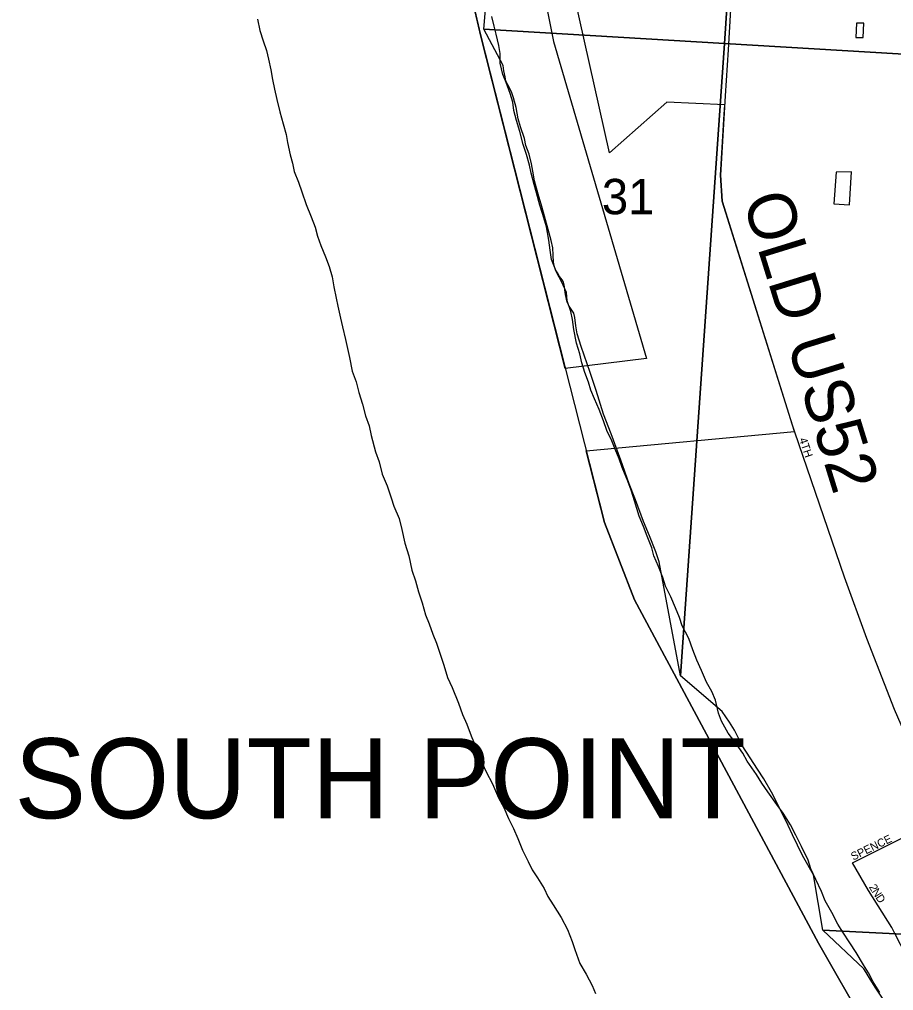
# Model space of a CAD drawing. Extents: x 1949938.81 to 1949945.61, y 152207.65 to 152214.09.
# Drawn here: x 1949939.393 to 1949940.427, y 152209.158 to 152210.308 of the extents above; entities that cross this region are included whole.
import ezdxf

# ---------------------------------------------------------------- set-up
doc = ezdxf.new("R2010")
doc.units = 0
for name, color, linetype in [('GM_X_City_Street', 7, 'Continuous'), ('GM_X_City_Street_Text', 7, 'Continuous'), ('GM_X_Corporation', 7, 'Continuous'), ('GM_X_Corporation_Text', 7, 'Continuous'), ('GM_X_County', 7, 'Continuous'), ('GM_X_County_Road', 7, 'Continuous'), ('GM_X_County_Road_Text', 7, 'Continuous'), ('GM_X_Major_River', 7, 'Continuous'), ('GM_X_Section', 7, 'Continuous'), ('GM_X_Section_Text', 7, 'Continuous'), ('GM_X_Township', 7, 'Continuous')]:
    doc.layers.add(name, color=color, linetype=linetype)

msp = doc.modelspace()

# ---------------------------------------------------------------- linework, layer by layer
at = {"layer": 'GM_X_City_Street'}
for points in [[(1949940.2381, 152210.3883), (1949940.2314, 152210.2719), (1949940.2281, 152210.2175)], [(1949940.3073, 152209.828), (1949940.3099, 152209.8198), (1949940.3687, 152209.6481), (1949940.3953, 152209.5754), (1949940.428, 152209.4915), (1949940.4841, 152209.3624), (1949940.5115, 152209.3013), (1949940.5424, 152209.2289)], [(1949940.3786, 152209.3094), (1949940.4345, 152209.3375), (1949940.4841, 152209.3624)], [(1949940.4828, 152209.1185), (1949940.4627, 152209.1592), (1949940.4558, 152209.1732), (1949940.4287, 152209.2261), (1949940.4251, 152209.2332), (1949940.3975, 152209.2768), (1949940.3786, 152209.3094)]]:
    msp.add_lwpolyline(points, dxfattribs=at)
at = {"layer": 'GM_X_Corporation'}
for points in [[(1949939.8861, 152210.5185), (1949939.9781, 152210.5158), (1949940.0249, 152210.2816), (1949940.1348, 152209.9064), (1949940.0387, 152209.8948), (1949939.9388, 152210.288), (1949939.9215, 152210.363), (1949939.8931, 152210.4482)], [(1949940.3825, 152210.2866), (1949940.3911, 152210.2866), (1949940.3919, 152210.3034), (1949940.3833, 152210.3034)], [(1949940.375, 152210.0885), (1949940.3773, 152210.1274), (1949940.3594, 152210.127), (1949940.3564, 152210.0896)]]:
    msp.add_lwpolyline(points, close=True, dxfattribs=at)
msp.add_lwpolyline([(1949940.3947, 152209.1158), (1949940.3383, 152209.2145), (1949940.1207, 152209.6209), (1949940.0851, 152209.7125), (1949940.0635, 152209.7974), (1949940.3098, 152209.8201), (1949940.2242, 152210.0926), (1949940.2224, 152210.1234), (1949940.2269, 152210.1955), (1949940.2275, 152210.2069), (1949940.1588, 152210.2098), (1949940.0909, 152210.1498), (1949940.0091, 152210.5167)], dxfattribs=at)
at = {"layer": 'GM_X_County'}
msp.add_lwpolyline([(1949939.7311, 152211.8376), (1949939.7258, 152211.7457), (1949939.7413, 152211.6273), (1949939.7962, 152211.2639), (1949939.7977, 152211.2171), (1949939.8117, 152211.0959), (1949939.8776, 152210.6025), (1949939.8931, 152210.4482), (1949939.9215, 152210.363), (1949939.9378, 152210.2911), (1949940.0851, 152209.7125), (1949940.1207, 152209.6209), (1949940.3383, 152209.2145), (1949940.3947, 152209.1158)], dxfattribs=at)
at = {"layer": 'GM_X_County_Road'}
msp.add_lwpolyline([(1949940.2281, 152210.2175), (1949940.2224, 152210.1234), (1949940.2242, 152210.0926), (1949940.3073, 152209.828)], dxfattribs=at)
at = {"layer": 'GM_X_Major_River'}
for points in [[(1949939.6744, 152210.308), (1949939.6774, 152210.2947), (1949939.6812, 152210.2825), (1949939.685, 152210.2711), (1949939.6876, 152210.2608), (1949939.6903, 152210.2483), (1949939.6921, 152210.2365), (1949939.6944, 152210.2251), (1949939.6974, 152210.2129), (1949939.7008, 152210.1985), (1949939.705, 152210.1841), (1949939.7084, 152210.1715), (1949939.7099, 152210.162), (1949939.7133, 152210.1476), (1949939.716, 152210.1377), (1949939.7178, 152210.1278), (1949939.7228, 152210.1153), (1949939.7269, 152210.1038), (1949939.7322, 152210.0886), (1949939.7379, 152210.0742), (1949939.7428, 152210.062), (1949939.7454, 152210.0514), (1949939.7496, 152210.0404), (1949939.7549, 152210.0267), (1949939.7594, 152210.0153), (1949939.7628, 152210.0031), (1949939.7647, 152209.9913), (1949939.7674, 152209.978), (1949939.7696, 152209.9685), (1949939.7726, 152209.9541), (1949939.7749, 152209.9438), (1949939.7787, 152209.929), (1949939.781, 152209.9184), (1949939.7832, 152209.9077), (1949939.7866, 152209.8914), (1949939.7912, 152209.8789), (1949939.7942, 152209.8663), (1949939.7987, 152209.8526), (1949939.8021, 152209.8386), (1949939.8067, 152209.8268), (1949939.8089, 152209.8154), (1949939.8142, 152209.796), (1949939.8184, 152209.7843), (1949939.8222, 152209.7694), (1949939.8278, 152209.7558), (1949939.8327, 152209.7417), (1949939.8358, 152209.7318), (1949939.8422, 152209.717), (1949939.8452, 152209.7041), (1949939.849, 152209.6881), (1949939.8535, 152209.6729), (1949939.8573, 152209.6559), (1949939.8615, 152209.6433), (1949939.8649, 152209.6304), (1949939.8694, 152209.6175), (1949939.8732, 152209.6031), (1949939.8777, 152209.5924), (1949939.8819, 152209.5803), (1949939.8864, 152209.5696), (1949939.8909, 152209.5552), (1949939.8951, 152209.5434), (1949939.8992, 152209.529), (1949939.9049, 152209.5172), (1949939.9125, 152209.4986), (1949939.917, 152209.4853)], [(1949940.0585, 152209.9013), (1949940.0559, 152209.9119), (1949940.0521, 152209.9248), (1949940.0487, 152209.9408), (1949940.0472, 152209.9526), (1949940.0453, 152209.9621), (1949940.0411, 152209.9746), (1949940.04, 152209.9845), (1949940.0343, 152209.9978), (1949940.0287, 152210.008), (1949940.0226, 152210.0236), (1949940.0207, 152210.0346), (1949940.0192, 152210.0464), (1949940.0166, 152210.0624), (1949940.0117, 152210.078), (1949940.0086, 152210.0879), (1949940.0045, 152210.1027), (1949940.0018, 152210.1126), (1949939.9984, 152210.1259), (1949939.9962, 152210.1354), (1949939.9928, 152210.1479), (1949939.989, 152210.1597), (1949939.9848, 152210.1753), (1949939.981, 152210.1882), (1949939.978, 152210.2), (1949939.9765, 152210.2099), (1949939.9735, 152210.2201), (1949939.9689, 152210.2331), (1949939.9648, 152210.2426), (1949939.9618, 152210.2562), (1949939.9618, 152210.2673), (1949939.9599, 152210.2771), (1949939.9569, 152210.2905), (1949939.9546, 152210.3), (1949939.9516, 152210.3114)], [(1949940.4108, 152209.1562), (1949940.4032, 152209.1687), (1949940.3976, 152209.1794), (1949940.3915, 152209.1888), (1949940.3828, 152209.2033), (1949940.3753, 152209.215), (1949940.3673, 152209.2276), (1949940.3613, 152209.2371), (1949940.3541, 152209.2507), (1949940.3461, 152209.2648), (1949940.342, 152209.2758), (1949940.3352, 152209.2898), (1949940.3295, 152209.3023), (1949940.3261, 152209.3126), (1949940.3182, 152209.3289), (1949940.3114, 152209.3422), (1949940.3053, 152209.3544), (1949940.2966, 152209.3684), (1949940.2891, 152209.3786), (1949940.2785, 152209.3935), (1949940.2713, 152209.4037), (1949940.2649, 152209.4143), (1949940.2539, 152209.4299), (1949940.249, 152209.4394), (1949940.2392, 152209.4527), (1949940.2316, 152209.4629), (1949940.2237, 152209.4774), (1949940.2199, 152209.4869), (1949940.2165, 152209.502), (1949940.2123, 152209.5123), (1949940.2059, 152209.5233), (1949940.1999, 152209.5374), (1949940.1946, 152209.5495), (1949940.1897, 152209.5617), (1949940.1848, 152209.575), (1949940.1772, 152209.5901), (1949940.1738, 152209.6), (1949940.1693, 152209.6114), (1949940.1636, 152209.6243), (1949940.1572, 152209.6372), (1949940.1541, 152209.6471), (1949940.1492, 152209.6604), (1949940.1436, 152209.6729), (1949940.1413, 152209.6824), (1949940.1356, 152209.6961), (1949940.1311, 152209.7075), (1949940.1262, 152209.72), (1949940.1205, 152209.7379), (1949940.1167, 152209.7508), (1949940.1126, 152209.7614), (1949940.1061, 152209.7774), (1949940.1024, 152209.7877), (1949940.0978, 152209.7991), (1949940.0937, 152209.8089), (1949940.088, 152209.8211), (1949940.0838, 152209.8329), (1949940.0789, 152209.8462), (1949940.0733, 152209.8587), (1949940.0691, 152209.869), (1949940.0661, 152209.8785), (1949940.0619, 152209.8899), (1949940.0585, 152209.9013)], [(1949939.917, 152209.4853), (1949939.9223, 152209.4736), (1949939.9272, 152209.4599), (1949939.9321, 152209.4485), (1949939.9363, 152209.4364), (1949939.945, 152209.4174), (1949939.9525, 152209.4029), (1949939.9597, 152209.3866), (1949939.9658, 152209.3752), (1949939.9714, 152209.3619), (1949939.9775, 152209.3502), (1949939.9824, 152209.3384), (1949939.9881, 152209.3244), (1949939.9949, 152209.3111), (1949939.9994, 152209.3012), (1949940.0058, 152209.2917), (1949940.0138, 152209.2792), (1949940.0179, 152209.2697), (1949940.0243, 152209.2598), (1949940.0338, 152209.245), (1949940.0414, 152209.2306), (1949940.047, 152209.2166), (1949940.05, 152209.2071), (1949940.0561, 152209.1904), (1949940.0633, 152209.1778), (1949940.0705, 152209.1646), (1949940.0746, 152209.1551)]]:
    msp.add_lwpolyline(points, dxfattribs=at)
at = {"layer": 'GM_X_Section'}
for points in [[(1949940.2943, 152211.2945), (1949940.227, 152210.2792), (1949939.9424, 152210.2964), (1949939.9466, 152210.3476)], [(1949940.4149, 152209.1481), (1949940.4062, 152209.1614), (1949940.3994, 152209.172), (1949940.3948, 152209.1796), (1949940.3922, 152209.1841), (1949940.3437, 152209.23), (1949941.2772, 152209.1831), (1949941.2271, 152208.3769)]]:
    msp.add_lwpolyline(points, dxfattribs=at)
for points in [[(1949941.3926, 152211.2226), (1949941.3344, 152210.2133), (1949940.227, 152210.2792), (1949940.2943, 152211.2945)], [(1949940.227, 152210.2792), (1949940.1749, 152209.5309), (1949940.15, 152209.6658), (1949940.1459, 152209.6776), (1949940.1383, 152209.6965), (1949940.1311, 152209.7136), (1949940.1217, 152209.7394), (1949940.1145, 152209.7583), (1949940.1046, 152209.7863), (1949940.0929, 152209.8174), (1949940.0838, 152209.8405), (1949940.0751, 152209.8686), (1949940.068, 152209.8898), (1949940.0577, 152209.9205), (1949940.0528, 152209.9357), (1949940.0513, 152209.9451), (1949940.0502, 152209.955), (1949940.0487, 152209.9603), (1949940.0434, 152209.9686), (1949940.0411, 152209.9732), (1949940.04, 152209.9766), (1949940.0388, 152209.9823), (1949940.0373, 152209.9936), (1949940.0366, 152209.9967), (1949940.0351, 152209.9997), (1949940.032, 152210.0035), (1949940.0294, 152210.0077), (1949940.0271, 152210.0115), (1949940.026, 152210.0149), (1949940.0249, 152210.0206), (1949940.0245, 152210.0289), (1949940.0241, 152210.0376), (1949940.0222, 152210.0463), (1949940.0184, 152210.0592), (1949940.0109, 152210.0865), (1949940.0067, 152210.1009), (1949940.0022, 152210.1168), (1949940.0003, 152210.1282), (1949939.9988, 152210.1369), (1949939.9958, 152210.1483), (1949939.992, 152210.1585), (1949939.9905, 152210.1668), (1949939.9859, 152210.1805), (1949939.9829, 152210.1903), (1949939.9806, 152210.2036), (1949939.9776, 152210.2149), (1949939.975, 152210.2221), (1949939.9708, 152210.2305), (1949939.9685, 152210.235), (1949939.9674, 152210.24), (1949939.9659, 152210.2468), (1949939.9651, 152210.2532), (1949939.9424, 152210.2964)], [(1949940.227, 152210.2792), (1949941.3344, 152210.2133), (1949941.2772, 152209.1831), (1949940.3437, 152209.23), (1949940.3324, 152209.2952), (1949940.3195, 152209.3183), (1949940.3078, 152209.3429), (1949940.3025, 152209.3539), (1949940.2934, 152209.3725), (1949940.2828, 152209.3933), (1949940.2737, 152209.4089), (1949940.2662, 152209.4206), (1949940.2575, 152209.4339), (1949940.248, 152209.4483), (1949940.2389, 152209.4665), (1949940.2332, 152209.476), (1949940.2245, 152209.4885), (1949940.1749, 152209.5309)]]:
    msp.add_lwpolyline(points, close=True, dxfattribs=at)
at = {"layer": 'GM_X_Township'}
msp.add_lwpolyline([(1949939.7311, 152211.8376), (1949939.7258, 152211.7457), (1949939.7413, 152211.6273), (1949939.7962, 152211.2639), (1949939.7977, 152211.2171), (1949939.8117, 152211.0959), (1949939.8776, 152210.6025), (1949939.8931, 152210.4482), (1949939.9215, 152210.363), (1949939.9378, 152210.2911), (1949940.0851, 152209.7125), (1949940.1207, 152209.6209), (1949940.3383, 152209.2145), (1949940.3947, 152209.1158)], dxfattribs=at)

# ---------------------------------------------------------------- texts
at = {"layer": 'GM_X_City_Street_Text'}
for s, rotation, p in [('4TH', 288.4418, (1949940.3153, 152209.811)), ('SPENCE', 26.0749, (1949940.3795, 152209.3121)), ('2', 299.6597, (1949940.3978, 152209.2811)), ('N', 302.7536, (1949940.401, 152209.2756)), ('D', 303.0449, (1949940.4055, 152209.2685))]:
    msp.add_text(s, height=0.00947, rotation=rotation, dxfattribs=at).set_placement(p)
at = {"layer": 'GM_X_Corporation_Text'}
msp.add_text('SOUTH POINT', height=0.094697, rotation=0, dxfattribs=at).set_placement((1949939.387, 152209.3623))
at = {"layer": 'GM_X_County_Road_Text'}
msp.add_text('OLD US52', height=0.05682, rotation=287.2024, dxfattribs=at).set_placement((1949940.2483, 152210.0946))
at = {"layer": 'GM_X_Section_Text'}
msp.add_text('31', height=0.04186, rotation=0, dxfattribs=at).set_placement((1949940.082, 152210.0772))

doc.saveas('drawing.dxf')
